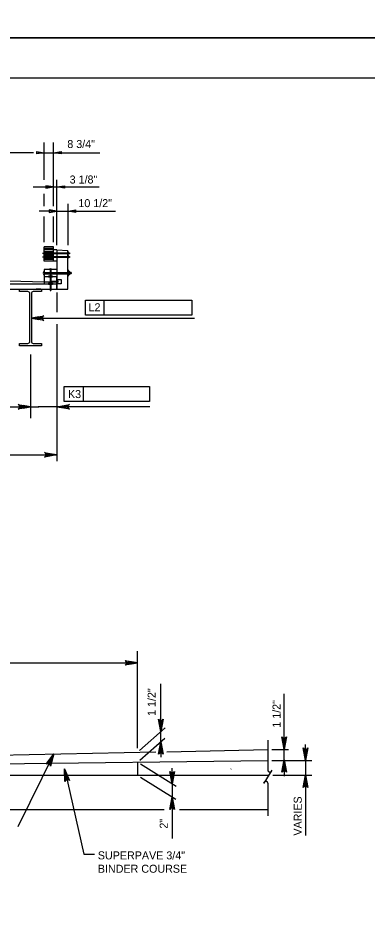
# Model space of a CAD drawing. Extents: x 638175 to 640495, y 294277 to 298435.
# Drawn here: x 638680.6 to 638811.4, y 296327.6 to 296661 of the extents above; entities that cross this region are included whole.
import ezdxf

# ---------------------------------------------------------------- set-up
doc = ezdxf.new("R2010")
doc.units = 0
for name, color, linetype in [('2', 7, 'Continuous'), ('3', 7, 'Continuous'), ('4', 7, 'Continuous'), ('6', 7, 'Continuous'), ('PLT-BNDY', 7, 'Continuous')]:
    doc.layers.add(name, color=color, linetype=linetype)

msp = doc.modelspace()

# ---------------------------------------------------------------- linework, layer by layer
at = {"layer": '2'}
for p, q in [((638475.46, 296638.46), (639261.46, 296638.46)), ((638690.48, 296600.26), (638690.48, 296614.24)), ((638693.95, 296590.38), (638693.95, 296614.24)), ((638686.45, 296610.39), (638559.36, 296610.39)), ((638688.04, 296610.39), (638711.27, 296610.39)), ((638695.18, 296575.77), (638695.18, 296600.26)), ((638686.28, 296597.55), (638711.07, 296597.55)), ((638690.48, 296590.38), (638690.48, 296595.03)), ((638699.35, 296591.29), (638699.35, 296575.77)), ((638695.18, 296588.49), (638688.53, 296588.49)), ((638690.48, 296576.86), (638690.48, 296586.46)), ((638693.95, 296576.86), (638693.95, 296586.46)), ((638695.18, 296588.49), (638717.14, 296588.49)), ((638693.95, 296575.14), (638690.48, 296575.14)), ((638690.48, 296569.78), (638690.48, 296575.14)), ((638693.95, 296574.55), (638690.48, 296574.55)), ((638693.95, 296573.95), (638690.48, 296573.95)), ((638690.48, 296573.36), (638693.95, 296573.36)), ((638690.48, 296572.91), (638699.35, 296572.91)), ((638690.48, 296572.62), (638699.35, 296572.62)), ((638693.95, 296569.78), (638693.95, 296575.14)), ((638695.18, 296573.95), (638693.95, 296573.95)), ((638695.18, 296573.95), (638699.35, 296573.76)), ((638695.18, 296573.95), (638695.18, 296566.61)), ((638695.18, 296573.95), (638699.35, 296573.76)), ((638699.35, 296559.29), (638699.35, 296573.76)), ((638699.45, 296573.36), (638699.35, 296573.36)), ((638699.45, 296572.17), (638699.45, 296573.36)), ((638699.45, 296572.53), (638699.45, 296572.99)), ((638699.65, 296572.99), (638699.45, 296572.99)), ((638699.65, 296572.87), (638699.45, 296572.87)), ((638699.65, 296572.64), (638699.45, 296572.64)), ((638699.65, 296572.53), (638699.45, 296572.53)), ((638699.68, 296572.93), (638699.68, 296572.59)), ((638699.68, 296572.93), (638699.68, 296572.59)), ((638699.68, 296572.91), (638699.86, 296572.91)), ((638699.68, 296572.61), (638699.86, 296572.61)), ((638699.89, 296572.88), (638699.86, 296572.91)), ((638699.89, 296572.63), (638699.86, 296572.61)), ((638699.89, 296572.88), (638699.89, 296572.63)), ((638690.48, 296572.17), (638693.95, 296572.17)), ((638690.48, 296571.57), (638693.95, 296571.57)), ((638690.48, 296571.52), (638699.35, 296571.52)), ((638690.48, 296571.22), (638699.35, 296571.22)), ((638690.48, 296570.98), (638693.95, 296570.98)), ((638693.95, 296570.38), (638690.48, 296570.38)), ((638695.18, 296569.78), (638690.48, 296569.78)), ((638699.35, 296572.17), (638699.35, 296572.17)), ((638699.35, 296572.17), (638699.45, 296572.17)), ((638699.45, 296571.97), (638699.35, 296571.97)), ((638699.35, 296570.77), (638699.35, 296570.77)), ((638699.35, 296570.77), (638699.45, 296570.77)), ((638699.45, 296572.17), (638699.45, 296572.17)), ((638699.45, 296570.77), (638699.45, 296571.97)), ((638699.45, 296571.14), (638699.45, 296571.6)), ((638699.65, 296571.6), (638699.45, 296571.6)), ((638699.65, 296571.48), (638699.45, 296571.48)), ((638699.65, 296571.25), (638699.45, 296571.25)), ((638699.65, 296571.14), (638699.45, 296571.14)), ((638699.45, 296570.77), (638699.45, 296570.77)), ((638699.68, 296571.54), (638699.68, 296571.2)), ((638699.68, 296571.54), (638699.68, 296571.2)), ((638699.68, 296571.52), (638699.86, 296571.52)), ((638699.68, 296571.22), (638699.86, 296571.22)), ((638699.89, 296571.5), (638699.86, 296571.52)), ((638699.89, 296571.25), (638699.86, 296571.22)), ((638699.89, 296571.5), (638699.89, 296571.25)), ((638695.18, 296566.61), (638690.42, 296566.61)), ((638690.42, 296566.61), (638690.42, 296563.93)), ((638690.42, 296565.51), (638699.35, 296565.51)), ((638692.66, 296566.61), (638692.66, 296559.29)), ((638692.8, 296558.78), (638692.8, 296566.96)), ((638692.96, 296566.61), (638692.96, 296559.29)), ((638695.18, 296566.61), (638695.18, 296563.93)), ((638699.35, 296566.46), (638699.35, 296564.08)), ((638699.35, 296566.46), (638699.45, 296566.46)), ((638699.35, 296565.54), (638699.45, 296565.54)), ((638699.45, 296566.46), (638699.45, 296564.08)), ((638699.45, 296565.82), (638699.45, 296564.72)), ((638699.94, 296565.82), (638699.45, 296565.82)), ((638699.95, 296565.54), (638699.45, 296565.54)), ((638700.04, 296564.86), (638700.04, 296565.68)), ((638700.04, 296565.51), (638700.04, 296565.51)), ((638700.04, 296565.51), (638700.44, 296565.51)), ((638700.48, 296565.47), (638700.44, 296565.51)), ((638690.42, 296565.02), (638699.35, 296565.02)), ((638690.42, 296563.93), (638690.42, 296561.25)), ((638695.18, 296563.93), (638690.42, 296563.93)), ((638692.01, 296564.13), (638692.01, 296563.73)), ((638693.6, 296564.13), (638692.01, 296564.13)), ((638693.6, 296563.73), (638692.01, 296563.73)), ((638693.6, 296564.13), (638693.6, 296563.73)), ((638695.18, 296563.93), (638695.18, 296561.25)), ((638695.18, 296562.84), (638696.78, 296562.84)), ((638695.37, 296562.84), (638695.37, 296561.25)), ((638695.43, 296562.34), (638695.37, 296562.34)), ((638695.43, 296562.34), (638695.43, 296561.74)), ((638695.43, 296562.24), (638695.57, 296562.24)), ((638695.57, 296562.24), (638695.57, 296561.85)), ((638696.78, 296562.84), (638696.78, 296561.25)), ((638699.35, 296565), (638699.45, 296565)), ((638699.45, 296564.08), (638699.35, 296564.08)), ((638699.95, 296565), (638699.45, 296565)), ((638699.94, 296564.72), (638699.45, 296564.72)), ((638700.44, 296565.02), (638700.04, 296565.02)), ((638700.48, 296565.07), (638700.44, 296565.02)), ((638700.48, 296565.47), (638700.48, 296565.07)), ((638690.42, 296562.06), (638695.18, 296562.06)), ((638692.01, 296561.45), (638692.01, 296561.05)), ((638693.6, 296561.45), (638692.01, 296561.45)), ((638693.6, 296561.05), (638692.01, 296561.05)), ((638692.21, 296559.19), (638692.21, 296559.29)), ((638693.41, 296559.19), (638692.21, 296559.19)), ((638692.57, 296558.99), (638692.57, 296559.19)), ((638692.63, 296559.29), (638692.63, 296559.19)), ((638692.63, 296558.96), (638692.98, 296558.96)), ((638692.66, 296558.96), (638692.66, 296558.78)), ((638692.93, 296558.93), (638692.68, 296558.93)), ((638692.93, 296558.91), (638692.68, 296558.91)), ((638692.93, 296558.88), (638692.68, 296558.88)), ((638692.93, 296558.86), (638692.68, 296558.86)), ((638692.69, 296558.99), (638692.69, 296559.19)), ((638692.92, 296558.99), (638692.92, 296559.19)), ((638692.96, 296558.96), (638692.96, 296558.78)), ((638692.99, 296559.29), (638692.99, 296559.19)), ((638693.03, 296558.99), (638693.03, 296559.19)), ((638693.04, 296562.04), (638693.26, 296562.16)), ((638693.04, 296562.04), (638693.26, 296561.91)), ((638695.37, 296562.16), (638693.26, 296562.16)), ((638695.37, 296561.91), (638693.26, 296561.91)), ((638693.41, 296559.29), (638693.41, 296559.29)), ((638693.41, 296559.29), (638693.41, 296559.19)), ((638693.41, 296559.2), (638693.41, 296559.2)), ((638693.6, 296561.45), (638693.6, 296561.05)), ((638696.78, 296561.25), (638695.18, 296561.25)), ((638695.18, 296561.25), (638695.18, 296559.29)), ((638695.43, 296561.74), (638695.37, 296561.74)), ((638695.43, 296561.85), (638695.57, 296561.85)), ((638692.68, 296558.76), (638692.66, 296558.78)), ((638692.93, 296558.83), (638692.68, 296558.83)), ((638692.93, 296558.8), (638692.68, 296558.8)), ((638692.93, 296558.78), (638692.68, 296558.78)), ((638692.68, 296558.76), (638692.93, 296558.76)), ((638692.93, 296558.76), (638692.96, 296558.78)), ((638695.18, 296558.01), (638695.18, 296550.61)), ((638695.18, 296546.19), (638695.18, 296494.83)), ((638685.34, 296534.79), (638685.34, 296512.32)), ((638685.34, 296521.08), (638685.34, 296510.92)), ((638553.45, 296515.17), (638688.41, 296515.17)), ((638729.95, 296515.17), (638688.18, 296515.17)), ((638553.45, 296497.2), (638695.18, 296497.2)), ((638695.18, 296497.2), (638695.18, 296497.2)), ((638774.15, 296390.18), (638774.15, 296379.01)), ((638774.15, 296374.15), (638774.15, 296361.85))]:
    msp.add_line(p, q, dxfattribs=at)
for points in [[(638696.78, 296610.86), (638696.78, 296609.92), (638693.95, 296610.39)], [(638691.11, 296598.02), (638691.11, 296597.07), (638693.95, 296597.55)], [(638698.02, 296598.02), (638698.02, 296597.07), (638695.18, 296597.55)], [(638692.35, 296588.96), (638692.35, 296588.01), (638695.18, 296588.49)], [(638702.19, 296588.96), (638702.19, 296588.01), (638699.36, 296588.49)], [(638682.51, 296515.64), (638682.51, 296514.7), (638685.34, 296515.17)], [(638692.56, 296496.76), (638692.56, 296497.63), (638695.18, 296497.2)]]:
    msp.add_lwpolyline(points, close=True, dxfattribs=at)
for points in [[(638685.63, 296548.41), (638690.29, 296549.28), (638689.93, 296549.03), (638689.75, 296548.72), (638689.69, 296548.41), (638689.75, 296548.1), (638689.93, 296547.78), (638690.29, 296547.54), (638685.63, 296548.41), (638689.93, 296547.78), (638689.75, 296548.1), (638685.63, 296548.41), (638689.69, 296548.41), (638689.75, 296548.72), (638685.63, 296548.41), (638689.93, 296549.03)], [(638685.34, 296515.17), (638680.68, 296514.3), (638681.04, 296514.55), (638681.23, 296514.86), (638681.28, 296515.17), (638681.23, 296515.48), (638681.04, 296515.8), (638680.68, 296516.04), (638685.34, 296515.17), (638681.04, 296515.8), (638681.23, 296515.48), (638685.34, 296515.17), (638681.28, 296515.17), (638681.23, 296514.86), (638685.34, 296515.17), (638681.04, 296514.55)], [(638695.18, 296515.17), (638699.85, 296516.04), (638699.49, 296515.8), (638699.3, 296515.48), (638699.25, 296515.17), (638699.3, 296514.86), (638699.49, 296514.55), (638699.85, 296514.3), (638695.18, 296515.17), (638699.49, 296514.55), (638699.3, 296514.86), (638695.18, 296515.17), (638699.25, 296515.17), (638699.3, 296515.48), (638695.18, 296515.17), (638699.49, 296515.8)], [(638695.18, 296497.2), (638690.52, 296496.32), (638690.88, 296496.57), (638691.07, 296496.88), (638691.12, 296497.2), (638691.07, 296497.51), (638690.88, 296497.82), (638690.52, 296498.07), (638695.18, 296497.2), (638690.88, 296497.82), (638691.07, 296497.51), (638695.18, 296497.2), (638691.12, 296497.2), (638691.07, 296496.88), (638695.18, 296497.2), (638690.88, 296496.57)], [(638775.48, 296378.65), (638775.67, 296378.95), (638772.64, 296374.14), (638772.85, 296374.46)]]:
    msp.add_lwpolyline(points, dxfattribs=at)
for centre, radius, start, end in [((638691.14, 296572.76), 0.898, 138.5212, 221.4788), ((638699.49, 296572.76), 0.195, 323.9035, 35.4998), ((638699.62, 296572.59), 0.0631, 294.7299, 65.8765), ((638699.62, 296572.93), 0.0634, 295.2914, 65.298), ((638691.14, 296571.37), 0.898, 138.5212, 221.4788), ((638699.49, 296571.37), 0.195, 323.9035, 35.4998), ((638699.62, 296571.2), 0.0631, 294.7299, 65.8765), ((638699.62, 296571.54), 0.0634, 295.2914, 65.298), ((638690.89, 296565.27), 0.852, 123.281, 236.7201), ((638692.8, 296565.93), 0.898, 48.5212, 131.4788), ((638699.88, 296565.68), 0.151, 294.1303, 66.5922), ((638699.57, 296565.27), 0.469, 324.4913, 36.1094), ((638699.88, 296564.86), 0.152, 290.9772, 64.7169), ((638692.63, 296559.02), 0.0634, 204.702, 334.7086), ((638692.8, 296559.15), 0.195, 234.5002, 306.0965), ((638692.98, 296559.02), 0.0631, 204.1235, 335.2701), ((638774.87, 296379), 0.71, 180, 330), ((638773.45, 296374.08), 0.71, 5.3286, 147.8672)]:
    msp.add_arc(centre, radius, start, end, dxfattribs=at)
at = {"layer": '3'}
for p, q in [((638689.85, 296572.76), (638700.15, 296572.76)), ((638695.18, 296573.95), (638695.18, 296559.29)), ((638695.18, 296573.95), (638695.18, 296559.29)), ((638689.85, 296571.38), (638700.15, 296571.38)), ((638625.3, 296563.96), (638690.42, 296562.04)), ((638695.18, 296559.29), (638695.18, 296563.71)), ((638549.28, 296559.29), (638699.35, 296559.29)), ((638553.45, 296561.25), (638695.18, 296561.25)), ((638683.29, 296559.29), (638687.39, 296559.29)), ((638689.2, 296559.29), (638687.39, 296559.29)), ((638695.18, 296559.29), (638695.18, 296559.29)), ((638685.06, 296539.66), (638685.06, 296557.63)), ((638685.63, 296557.63), (638685.63, 296539.66)), ((638540.82, 296382.01), (638732.17, 296385.84)), ((638736.41, 296385.93), (638774.15, 296386.68)), ((638554.15, 296379.73), (638774.15, 296382.67)), ((638725.37, 296382.01), (638725.37, 296377.09)), ((638542.34, 296377.09), (638774.5, 296377.09)), ((638560.04, 296364.3), (638735.33, 296364.3)), ((638741.04, 296364.3), (638774.15, 296364.3))]:
    msp.add_line(p, q, dxfattribs=at)
for points in [[(638684.32, 296558.37), (638681.2, 296558.37), (638681.2, 296559.29), (638689.49, 296559.29), (638689.49, 296558.37), (638686.37, 296558.37)], [(638681.2, 296538), (638681.2, 296538.92), (638684.32, 296538.92)], [(638686.37, 296538.92), (638689.49, 296538.92), (638689.49, 296538), (638681.2, 296538)]]:
    msp.add_lwpolyline(points, dxfattribs=at)
for centre, start, end in [((638684.32, 296557.63), 0, 90), ((638686.37, 296557.63), 90, 180), ((638684.32, 296539.66), 270, 0), ((638686.37, 296539.66), 180, 270)]:
    msp.add_arc(centre, 0.738, start, end, dxfattribs=at)
at = {"layer": '4'}
for p, q in [((638705.87, 296555.08), (638745.74, 296555.08)), ((638705.87, 296549.55), (638705.87, 296555.08)), ((638712.92, 296549.55), (638712.92, 296555.08)), ((638745.74, 296555.08), (638745.74, 296549.55)), ((638745.74, 296549.55), (638705.87, 296549.55)), ((638685.63, 296548.41), (638746.67, 296548.41)), ((638697.93, 296522.74), (638729.88, 296522.74)), ((638697.93, 296517.2), (638697.93, 296522.74)), ((638705.21, 296517.2), (638705.21, 296522.74)), ((638729.88, 296522.74), (638729.88, 296517.2)), ((638729.88, 296517.2), (638697.93, 296517.2)), ((638725.37, 296395.01), (638725.37, 296423.59)), ((638540.82, 296419.16), (638725.37, 296419.16)), ((638734.13, 296396.38), (638734.13, 296411.41)), ((638780.28, 296389.63), (638780.28, 296407.63)), ((638725.37, 296387.24), (638725.37, 296395.19)), ((638726.15, 296386.38), (638735.77, 296394.83)), ((638734.13, 296389.74), (638734.13, 296393.43)), ((638726.25, 296382.79), (638735.58, 296390.98)), ((638734.13, 296386.78), (638734.13, 296383.83)), ((638775.69, 296386.68), (638781.86, 296386.68)), ((638780.28, 296382.67), (638780.28, 296386.68)), ((638788.3, 296385.62), (638788.3, 296388.57)), ((638775.69, 296382.67), (638790.61, 296382.67)), ((638775.69, 296382.67), (638784.71, 296382.67)), ((638788.3, 296382.67), (638788.3, 296377.09)), ((638726.51, 296381.31), (638739.89, 296372.99)), ((638738.33, 296376.82), (638738.33, 296379.77)), ((638780.28, 296379.71), (638780.28, 296376.76)), ((638726.44, 296376.43), (638739.76, 296368.15)), ((638776.04, 296377.09), (638790.61, 296377.09)), ((638738.33, 296373.86), (638738.33, 296368.94)), ((638788.3, 296374.14), (638788.3, 296354.46)), ((638738.33, 296365.99), (638738.33, 296353.42)), ((638705.24, 296347.53), (638709.25, 296347.53))]:
    msp.add_line(p, q, dxfattribs=at)
for points in [[(638688.46, 296547.94), (638688.46, 296548.88), (638685.63, 296548.41)], [(638722.41, 296419.66), (638722.41, 296418.67), (638725.37, 296419.16)], [(638733.64, 296396.38), (638734.62, 296396.38), (638734.13, 296393.43)], [(638733.64, 296386.78), (638734.62, 296386.78), (638734.13, 296389.74)], [(638779.79, 296389.63), (638780.77, 296389.63), (638780.28, 296386.68)], [(638787.81, 296385.62), (638788.8, 296385.62), (638788.3, 296382.67)], [(638779.79, 296379.71), (638780.77, 296379.71), (638780.28, 296382.67)], [(638691.15, 296379.24), (638691.07, 296379.15), (638691.12, 296379.12)], [(638760.38, 296379.45), (638760.3, 296379.36), (638760.35, 296379.33)], [(638737.84, 296376.82), (638738.82, 296376.82), (638738.33, 296373.86)], [(638787.81, 296374.14), (638788.8, 296374.14), (638788.3, 296377.09)], [(638737.84, 296365.99), (638738.82, 296365.99), (638738.33, 296368.94)]]:
    msp.add_lwpolyline(points, close=True, dxfattribs=at)
for points in [[(638725.37, 296419.16), (638720.71, 296418.29), (638721.06, 296418.54), (638721.25, 296418.85), (638721.3, 296419.16), (638721.25, 296419.48), (638721.06, 296419.79), (638720.71, 296420.04), (638725.37, 296419.16), (638721.06, 296419.79), (638721.25, 296419.48), (638725.37, 296419.16), (638721.3, 296419.16), (638721.25, 296418.85), (638725.37, 296419.16), (638721.06, 296418.54)], [(638734.13, 296393.45), (638733.25, 296398.11), (638733.5, 296397.75), (638733.82, 296397.56), (638734.13, 296397.51), (638734.44, 296397.56), (638734.75, 296397.75), (638735, 296398.11), (638734.13, 296393.45), (638734.75, 296397.75), (638734.44, 296397.56), (638734.13, 296393.45), (638734.13, 296397.51), (638733.82, 296397.56), (638734.13, 296393.45), (638733.5, 296397.75)], [(638734.15, 296389.6), (638735.03, 296384.94), (638734.78, 296385.3), (638734.47, 296385.48), (638734.15, 296385.53), (638733.84, 296385.48), (638733.53, 296385.3), (638733.28, 296384.94), (638734.15, 296389.6), (638733.53, 296385.3), (638733.84, 296385.48), (638734.15, 296389.6), (638734.15, 296385.53), (638734.47, 296385.48), (638734.15, 296389.6), (638734.78, 296385.3)], [(638780.25, 296386.88), (638779.38, 296391.54), (638779.62, 296391.18), (638779.94, 296390.99), (638780.25, 296390.94), (638780.56, 296390.99), (638780.87, 296391.18), (638781.12, 296391.54), (638780.25, 296386.88), (638780.87, 296391.18), (638780.56, 296390.99), (638780.25, 296386.88), (638780.25, 296390.94), (638779.94, 296390.99), (638780.25, 296386.88), (638779.62, 296391.18)], [(638788.3, 296382.67), (638787.43, 296387.33), (638787.68, 296386.97), (638787.99, 296386.78), (638788.3, 296386.73), (638788.62, 296386.78), (638788.93, 296386.97), (638789.18, 296387.33), (638788.3, 296382.67), (638788.93, 296386.97), (638788.62, 296386.78), (638788.3, 296382.67), (638788.3, 296386.73), (638787.99, 296386.78), (638788.3, 296382.67), (638787.68, 296386.97)], [(638694.04, 296385.08), (638680.56, 296357.82)], [(638694.04, 296385.08), (638692.75, 296380.51), (638692.69, 296380.94), (638692.49, 296381.25), (638692.24, 296381.44), (638691.93, 296381.53), (638691.57, 296381.5), (638691.19, 296381.29), (638694.04, 296385.08), (638691.57, 296381.5), (638691.93, 296381.53), (638694.04, 296385.08), (638692.24, 296381.44), (638692.49, 296381.25), (638694.04, 296385.08), (638692.69, 296380.94)], [(638780.28, 296382.86), (638781.16, 296378.2), (638780.91, 296378.56), (638780.6, 296378.74), (638780.28, 296378.79), (638779.97, 296378.74), (638779.66, 296378.56), (638779.41, 296378.2), (638780.28, 296382.86), (638779.66, 296378.56), (638779.97, 296378.74), (638780.28, 296382.86), (638780.28, 296378.79), (638780.6, 296378.74), (638780.28, 296382.86), (638780.91, 296378.56)], [(638698.06, 296379.52), (638699.92, 296375.15), (638699.6, 296375.45), (638699.25, 296375.56), (638698.94, 296375.55), (638698.65, 296375.43), (638698.38, 296375.18), (638698.21, 296374.78), (638698.06, 296379.52), (638698.38, 296375.18), (638698.65, 296375.43), (638698.06, 296379.52), (638698.94, 296375.55), (638699.25, 296375.56), (638698.06, 296379.52), (638699.6, 296375.45)], [(638698.16, 296379.07), (638705.24, 296347.53)], [(638738.33, 296373.86), (638737.46, 296378.52), (638737.7, 296378.16), (638738.02, 296377.98), (638738.33, 296377.92), (638738.64, 296377.98), (638738.95, 296378.16), (638739.2, 296378.52), (638738.33, 296373.86), (638738.95, 296378.16), (638738.64, 296377.98), (638738.33, 296373.86), (638738.33, 296377.92), (638738.02, 296377.98), (638738.33, 296373.86), (638737.7, 296378.16)], [(638788.3, 296377.14), (638789.18, 296372.48), (638788.93, 296372.84), (638788.62, 296373.03), (638788.3, 296373.08), (638787.99, 296373.03), (638787.68, 296372.84), (638787.43, 296372.48), (638788.3, 296377.14), (638787.68, 296372.84), (638787.99, 296373.03), (638788.3, 296377.14), (638788.3, 296373.08), (638788.62, 296373.03), (638788.3, 296377.14), (638788.93, 296372.84)], [(638738.33, 296368.94), (638739.2, 296364.28), (638738.95, 296364.64), (638738.64, 296364.82), (638738.33, 296364.88), (638738.02, 296364.82), (638737.7, 296364.64), (638737.46, 296364.28), (638738.33, 296368.94), (638737.7, 296364.64), (638738.02, 296364.82), (638738.33, 296368.94), (638738.33, 296364.88), (638738.64, 296364.82), (638738.33, 296368.94), (638738.95, 296364.64)]]:
    msp.add_lwpolyline(points, dxfattribs=at)
at = {"layer": '6'}
msp.add_lwpolyline([(638687.64, 296609.92), (638687.64, 296610.86), (638690.48, 296610.39)], close=True, dxfattribs=at)
at = {"layer": 'PLT-BNDY'}
for points in [[(638435.46, 297247.46), (639276.46, 297247.46), (639276.46, 296653.46), (638435.46, 296653.46)], [(638435.46, 296653.46), (639276.46, 296653.46), (639276.46, 296059.46), (638435.46, 296059.46)]]:
    msp.add_lwpolyline(points, close=True, dxfattribs=at)

# ---------------------------------------------------------------- texts
at = {"layer": '4'}
for s, p in [('8 3/4"', (638699.1, 296612.15)), ('3 1/8"', (638699.97, 296598.85)), ('10 1/2"', (638703.24, 296590)), ('L2', (638707.05, 296550.98)), ('K3', (638699.34, 296518.44)), ('SUPERPAVE 3/4"', (638710.52, 296345.56)), ('BINDER COURSE', (638710.52, 296340.56))]:
    msp.add_text(s, height=3, dxfattribs=at).set_placement(p)
for s, p in [('1 1/2"', (638732.18, 296399.33)), ('1 1/2"', (638778.93, 296394.92)), ('VARIES', (638786.85, 296354.47)), ('2"', (638736.68, 296357.09))]:
    msp.add_text(s, height=3, rotation=90, dxfattribs=at).set_placement(p)

doc.saveas('drawing.dxf')
